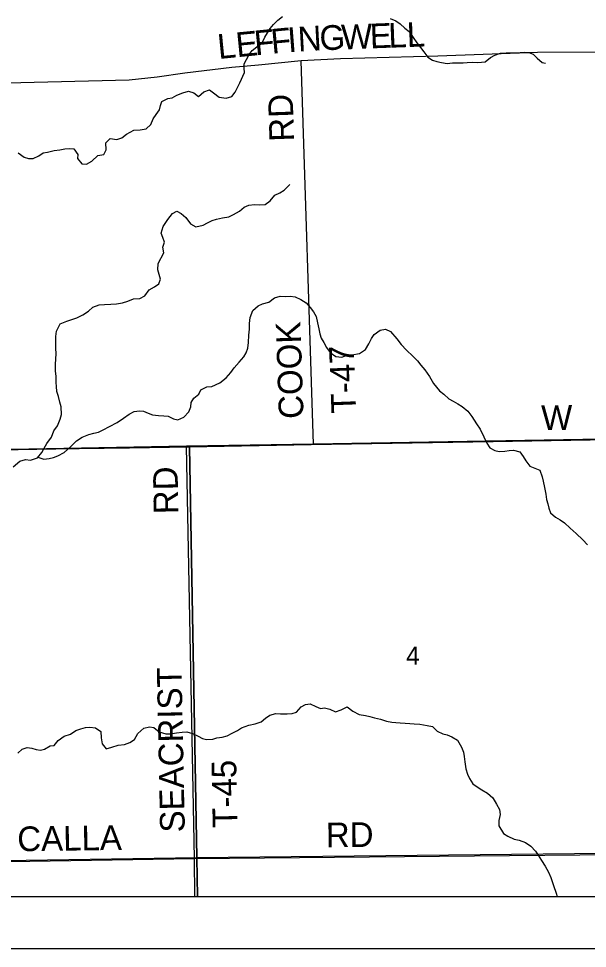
# Model space of a CAD drawing. Extents: x 0 to 34, y 0 to 22.
# Drawn here: x 5.396 to 6.705, y 13.887 to 16.025 of the extents above; entities that cross this region are included whole.
import ezdxf

# ---------------------------------------------------------------- set-up
doc = ezdxf.new("R2010")
doc.units = 0
for name, color, linetype in [('GM_X_Corporation', 7, 'Continuous'), ('GM_X_County_Road', 7, 'Continuous'), ('GM_X_County_Road_Text', 7, 'Continuous'), ('GM_X_Minor_River', 7, 'Continuous'), ('GM_X_Section_Text', 7, 'Continuous'), ('GM_X_Township_Road', 7, 'Continuous'), ('GM_X_Township_Road_Text', 7, 'Continuous'), ('SH_Data', 7, 'Continuous')]:
    doc.layers.add(name, color=color, linetype=linetype)

msp = doc.modelspace()

# ---------------------------------------------------------------- linework, layer by layer
at = {"layer": 'GM_X_Corporation'}
msp.add_lwpolyline([(2.9895, 20.1176), (2.9895, 14.989), (3.1061, 14.9902), (3.7218, 15.0051), (5.1362, 15.0301), (5.7825, 15.0418), (6.0746, 15.0468), (7.3134, 15.0684), (7.3375, 15.0689), (7.3129, 15.9614), (7.3097, 16.0633), (7.3049, 16.5704), (7.3046, 16.5913), (7.2998, 16.7507), (7.2943, 16.935), (7.2911, 17.0516), (7.2872, 17.1772), (7.283, 17.3071)], dxfattribs=at)
for points in [[(3.7367, 14.0069), (9.7895, 14.0069), (9.7895, 15.1275), (8.8365, 15.1033), (8.3803, 15.0917), (7.3375, 15.0689), (7.3134, 15.0684), (6.0746, 15.0468), (5.7825, 15.0418), (5.1362, 15.0301), (3.7218, 15.0051), (3.7359, 14.0555)], [(6.8006, 15.0584), (6.8205, 14.106), (5.8061, 14.0956), (5.789, 15.0408), (6.0694, 15.0457), (6.4885, 15.0527)], [(5.6513, 15.0385), (5.789, 15.0408), (5.8061, 14.0956), (4.774, 14.0793), (4.7584, 15.0257), (4.8116, 15.0266), (5.2442, 15.0326)], [(4.7752, 14.0069), (5.8075, 14.0069), (5.8061, 14.0956), (4.774, 14.0793)], [(5.8075, 14.0069), (6.8225, 14.0069), (6.8205, 14.106), (5.8061, 14.0956)]]:
    msp.add_lwpolyline(points, close=True, dxfattribs=at)
at = {"layer": 'GM_X_County_Road'}
msp.add_line((5.8019, 14.0069), (5.8006, 14.0939), dxfattribs=at)
for points in [[(3.722, 15.0045), (5.1364, 15.0296), (5.7827, 15.0412), (6.0748, 15.0463), (7.3136, 15.0678)], [(4.8042, 14.0781), (5.8006, 14.0939), (7.332, 14.1088)]]:
    msp.add_lwpolyline(points, dxfattribs=at)
at = {"layer": 'GM_X_Minor_River'}
for points in [[(5.9054, 15.8774), (5.9162, 15.9011), (5.9153, 15.9108), (5.9152, 15.9214), (5.9204, 15.9309), (5.9268, 15.9424), (5.9336, 15.952), (5.9483, 15.9635), (5.9581, 15.9723), (5.963, 15.9822), (5.9686, 15.9925), (5.975, 16.0021), (5.9825, 16.0117), (5.9927, 16.0212), (6.0032, 16.0301)], [(6.2509, 16.0253), (6.2639, 16.0197), (6.2738, 16.0133), (6.2846, 16.0031), (6.2945, 15.9956), (6.3038, 15.982), (6.3126, 15.9695), (6.3211, 15.9586), (6.3284, 15.9488), (6.338, 15.9367), (6.3484, 15.9292), (6.3587, 15.9262), (6.3693, 15.924), (6.3823, 15.9222), (6.3948, 15.9231), (6.4062, 15.9236), (6.4192, 15.9233), (6.4287, 15.9241), (6.4404, 15.925), (6.4526, 15.9243), (6.4701, 15.926), (6.4822, 15.9356), (6.492, 15.941), (6.5049, 15.9453), (6.5178, 15.9461), (6.5391, 15.9463), (6.5505, 15.9475), (6.5608, 15.948), (6.5703, 15.9469), (6.5799, 15.9432), (6.5898, 15.9338), (6.601, 15.924), (6.609, 15.9225)], [(5.3952, 15.7168), (5.4087, 15.7068), (5.4186, 15.7036), (5.4292, 15.7038), (5.4424, 15.7097), (5.4521, 15.7167), (5.4627, 15.7177), (5.4778, 15.7222), (5.491, 15.7232), (5.5027, 15.7253), (5.5129, 15.7267), (5.5232, 15.7253), (5.5321, 15.713), (5.5315, 15.7031), (5.5412, 15.6911), (5.5522, 15.6906), (5.5642, 15.6973), (5.5784, 15.7101), (5.592, 15.713), (5.5971, 15.723), (5.5968, 15.7397), (5.6069, 15.7494), (5.6221, 15.747), (5.6333, 15.751), (5.6442, 15.7592), (5.6614, 15.7683), (5.6754, 15.7697), (5.6898, 15.7715), (5.7006, 15.7819), (5.7057, 15.7946), (5.7127, 15.8046), (5.7201, 15.815), (5.7225, 15.8253), (5.7254, 15.8348), (5.7393, 15.8416), (5.7495, 15.8433), (5.7604, 15.8492), (5.7739, 15.8548), (5.7871, 15.8584), (5.7993, 15.8545), (5.8101, 15.846), (5.822, 15.8565), (5.8352, 15.8613), (5.8448, 15.8546), (5.8575, 15.8446), (5.8734, 15.8423), (5.8866, 15.8459), (5.894, 15.8556), (5.8995, 15.8663), (5.9054, 15.8774)], [(5.5183, 15.3336), (5.5296, 15.3373), (5.5439, 15.344), (5.557, 15.3526), (5.567, 15.3619), (5.5817, 15.3671), (5.5938, 15.3681), (5.6082, 15.3684), (5.6211, 15.369), (5.6354, 15.3716), (5.6471, 15.3752), (5.6603, 15.3808), (5.6747, 15.3815), (5.6863, 15.3878), (5.6967, 15.4013), (5.7086, 15.4087), (5.7184, 15.415), (5.7227, 15.4261), (5.7191, 15.4366), (5.7163, 15.4472), (5.7171, 15.462), (5.7303, 15.4862), (5.7278, 15.4995), (5.7314, 15.5113), (5.7278, 15.5215), (5.7238, 15.5317), (5.7288, 15.547), (5.7391, 15.5635), (5.7502, 15.577), (5.7604, 15.5822), (5.7703, 15.577), (5.7811, 15.5681), (5.7912, 15.5535), (5.8042, 15.5462), (5.8208, 15.5503), (5.8306, 15.5558), (5.8415, 15.5606), (5.8513, 15.5638), (5.8649, 15.5671), (5.8796, 15.5696), (5.8909, 15.5744), (5.904, 15.5826), (5.9152, 15.5912), (5.9261, 15.596), (5.939, 15.5974), (5.9515, 15.5969), (5.9636, 15.5975), (5.9752, 15.6064), (5.9855, 15.6188), (5.9972, 15.6247), (6.0069, 15.631), (6.02, 15.6434)], [(5.4403, 15.0165), (5.4541, 15.0122), (5.4659, 15.0139), (5.4761, 15.016), (5.4862, 15.0196), (5.5005, 15.0275), (5.515, 15.0407), (5.5295, 15.0546), (5.5419, 15.0629), (5.5573, 15.0689), (5.5694, 15.0717), (5.5799, 15.0746), (5.5908, 15.0794), (5.6055, 15.0869), (5.6227, 15.0963), (5.6377, 15.1065), (5.6504, 15.1159), (5.662, 15.1218), (5.6738, 15.1231), (5.6833, 15.1222), (5.6943, 15.1178), (5.7042, 15.1142), (5.7179, 15.1122), (5.7301, 15.1121), (5.7403, 15.1111), (5.7522, 15.1049), (5.7621, 15.1024), (5.776, 15.1084), (5.7875, 15.1208), (5.7926, 15.1327), (5.7931, 15.1425), (5.7994, 15.1525), (5.8106, 15.1615), (5.8157, 15.1715), (5.8289, 15.1782), (5.8406, 15.1795), (5.859, 15.1879), (5.8736, 15.1992), (5.8847, 15.2115), (5.8921, 15.2219), (5.9032, 15.2351), (5.9144, 15.2474), (5.9199, 15.257), (5.9235, 15.267), (5.9247, 15.2807), (5.9256, 15.297), (5.9272, 15.3107), (5.9273, 15.324), (5.9286, 15.3381), (5.9351, 15.3542), (5.9471, 15.3647), (5.9572, 15.3691), (5.9715, 15.3731), (5.985, 15.3833), (5.9978, 15.3866), (6.0111, 15.3864), (6.0209, 15.3866), (6.0327, 15.3857), (6.0457, 15.3791), (6.0576, 15.3717), (6.0669, 15.3609), (6.075, 15.3512), (6.0809, 15.3399), (6.0842, 15.3255), (6.0867, 15.3119), (6.0892, 15.3006), (6.092, 15.2904), (6.0987, 15.2806), (6.1049, 15.269), (6.1131, 15.2573), (6.1258, 15.2481), (6.1402, 15.2468), (6.1523, 15.2512), (6.1629, 15.2518), (6.1802, 15.2548), (6.1945, 15.2642), (6.2022, 15.2777), (6.208, 15.2895), (6.2139, 15.2991), (6.2281, 15.3085), (6.2402, 15.3114), (6.2516, 15.3059), (6.2664, 15.2888), (6.2765, 15.2757), (6.2888, 15.2626), (6.3031, 15.2492), (6.3143, 15.2384), (6.322, 15.2283), (6.3306, 15.2174), (6.3415, 15.2021), (6.3512, 15.1863), (6.3644, 15.1694), (6.3744, 15.1613), (6.386, 15.1512), (6.396, 15.1454), (6.4067, 15.1395), (6.417, 15.1336), (6.4297, 15.1224), (6.4394, 15.1101), (6.45, 15.0936), (6.4582, 15.0808)], [(5.3832, 14.9945), (5.3989, 15.0073), (5.4121, 15.011), (5.4235, 15.0101), (5.4393, 15.0153), (5.4493, 15.0273), (5.4548, 15.0376), (5.4611, 15.048), (5.4714, 15.0626), (5.4768, 15.0772), (5.4853, 15.0891), (5.4919, 15.1041), (5.4947, 15.1151), (5.494, 15.1322), (5.4911, 15.1435), (5.4875, 15.156), (5.4838, 15.1681), (5.4829, 15.1791), (5.4823, 15.1886), (5.4821, 15.2019), (5.4807, 15.2155), (5.4808, 15.2303), (5.4817, 15.2417), (5.4822, 15.2551), (5.4816, 15.2668), (5.4818, 15.2801), (5.4819, 15.2938), (5.4828, 15.3063), (5.4912, 15.3232), (5.507, 15.3296), (5.5183, 15.3336)], [(6.4582, 15.0808), (6.4668, 15.0635), (6.4735, 15.0492), (6.4805, 15.0379), (6.492, 15.0321), (6.5023, 15.0296), (6.5148, 15.0302), (6.525, 15.032), (6.5352, 15.0329), (6.5497, 15.029), (6.5574, 15.0185), (6.5633, 15.0084), (6.5723, 14.996), (6.5837, 14.9913), (6.5952, 14.9869), (6.6007, 14.9715), (6.6032, 14.9616), (6.6061, 14.9473), (6.6091, 14.9314), (6.6112, 14.9193), (6.614, 14.9094), (6.6165, 14.8992), (6.6201, 14.889), (6.632, 14.8786), (6.6424, 14.8727), (6.6523, 14.8657), (6.6651, 14.8538), (6.6789, 14.8415), (6.6944, 14.827), (6.7056, 14.8151)], [(5.6974, 14.3966), (5.7069, 14.3952), (5.7193, 14.3852), (5.7349, 14.3806), (5.7455, 14.3808), (5.7595, 14.3826), (5.7727, 14.3847), (5.7833, 14.3849), (5.7962, 14.3817), (5.8089, 14.3752), (5.8188, 14.37), (5.8287, 14.3676), (5.8427, 14.3686), (5.8525, 14.3711), (5.8646, 14.3728), (5.8759, 14.3764), (5.8872, 14.3824), (5.8996, 14.3883), (5.9093, 14.3946), (5.9259, 14.4002), (5.9406, 14.4035), (5.9541, 14.4083), (5.9642, 14.4165), (5.9739, 14.4239), (5.9879, 14.4276), (5.9989, 14.4267), (6.0137, 14.4266), (6.0254, 14.4272), (6.0359, 14.4308), (6.0463, 14.4428), (6.0565, 14.4479), (6.0667, 14.4496), (6.0797, 14.4434), (6.0904, 14.4387), (6.1002, 14.4404), (6.112, 14.4376), (6.1254, 14.4314), (6.1385, 14.4362), (6.1521, 14.4425), (6.1655, 14.4325), (6.18, 14.4252), (6.1945, 14.4228), (6.204, 14.4207), (6.2147, 14.4171), (6.2287, 14.414), (6.2428, 14.4101), (6.255, 14.4076), (6.2645, 14.4067), (6.2744, 14.4057), (6.2857, 14.4052), (6.2967, 14.4046), (6.3066, 14.4037), (6.3191, 14.4028), (6.3366, 14.4001), (6.3488, 14.3973), (6.3596, 14.3868), (6.3726, 14.3806), (6.3821, 14.3782), (6.3932, 14.3734), (6.4062, 14.3657), (6.4156, 14.3503), (6.42, 14.3386), (6.4217, 14.3284), (6.423, 14.3163), (6.4256, 14.3), (6.4292, 14.2879), (6.4336, 14.2781), (6.4414, 14.2657), (6.451, 14.2591), (6.4621, 14.2521), (6.4755, 14.2443), (6.4875, 14.2332), (6.4961, 14.2193), (6.5024, 14.2065), (6.5045, 14.1955), (6.5013, 14.1814), (6.5012, 14.1688), (6.5117, 14.1516), (6.5221, 14.1453), (6.5366, 14.1387), (6.548, 14.1363), (6.5629, 14.1309), (6.5752, 14.122), (6.5856, 14.1112), (6.5918, 14.1014), (6.5996, 14.0894), (6.6078, 14.0763), (6.6153, 14.0624), (6.6208, 14.0507), (6.6268, 14.0322), (6.6328, 14.0145), (6.6352, 14.0069)], [(5.3943, 14.336), (5.4044, 14.345), (5.4153, 14.3494), (5.4263, 14.3477), (5.4362, 14.3448), (5.4461, 14.3427), (5.4559, 14.3452), (5.4682, 14.353), (5.4781, 14.354), (5.4873, 14.3656), (5.5008, 14.3753), (5.5151, 14.3801), (5.5278, 14.3884), (5.5391, 14.3924), (5.5497, 14.3952), (5.5595, 14.3958), (5.5728, 14.3945), (5.5851, 14.386), (5.5861, 14.3716), (5.5879, 14.3576), (5.5976, 14.346), (5.6104, 14.3497), (5.6247, 14.3549), (5.6395, 14.3559), (5.6523, 14.3604), (5.6627, 14.3678), (5.6701, 14.3812), (5.6839, 14.3936), (5.6974, 14.3966)]]:
    msp.add_lwpolyline(points, dxfattribs=at)
at = {"layer": 'GM_X_Township_Road'}
for p, q in [((6.0748, 15.0463), (6.0463, 15.9282)), ((5.8006, 14.0939), (5.7827, 15.0412))]:
    msp.add_line(p, q, dxfattribs=at)
msp.add_lwpolyline([(7.3131, 15.9608), (7.0513, 15.9556), (6.7947, 15.9481), (6.5899, 15.9475), (6.3611, 15.9388), (6.1369, 15.9328), (6.0463, 15.9282), (5.9481, 15.9181), (5.8864, 15.9123), (5.7783, 15.8996), (5.7151, 15.8908), (5.6504, 15.8839), (5.1195, 15.8708)], dxfattribs=at)
at = {"layer": 'SH_Data'}
msp.add_line((2.8945, 13.8873), (9.8945, 13.8873), dxfattribs=at)

# ---------------------------------------------------------------- texts
at = {"layer": 'GM_X_County_Road_Text'}
for s, height, rotation, p in [('W', 0.0568, 0.7248, (6.5991, 15.0788)), ('RD', 0.05682, 0.4936, (6.1033, 14.1197)), ('CALLA', 0.05682, 0.796, (5.3932, 14.1105))]:
    msp.add_text(s, height=height, rotation=rotation, dxfattribs=at).set_placement(p)
at = {"layer": 'GM_X_Section_Text'}
msp.add_text('4', height=0.0419, rotation=0, dxfattribs=at).set_placement((6.2877, 14.5394))
at = {"layer": 'GM_X_Township_Road_Text'}
for s, height, rotation, p in [('W', 0.0568, 2.1364, (6.1395, 15.954)), ('E', 0.0568, 2.1392, (6.2053, 15.9565)), ('L', 0.0568, 2.1347, (6.2478, 15.958)), ('L', 0.0568, 2.1392, (6.2902, 15.9596)), ('E', 0.0568, 5.586, (5.8986, 15.9362)), ('F', 0.0568, 5.5825, (5.9409, 15.9404)), ('F', 0.0568, 5.3768, (5.979, 15.9441)), ('I', 0.0568, 4.4071, (6.0169, 15.9476)), ('N', 0.0568, 3.1198, (6.0399, 15.9494)), ('G', 0.0568, 2.1533, (6.0895, 15.9521)), ('L', 0.0568, 5.5844, (5.8563, 15.9321)), ('RD', 0.05682, 91.9758, (6.0303, 15.7432)), ('COOK', 0.05682, 91.9414, (6.052, 15.1057)), ('T-47', 0.05682, 92.1213, (6.1729, 15.1185)), ('RD', 0.05682, 90.9872, (5.7637, 14.8861)), ('SEACRIST', 0.05682, 91.1631, (5.7786, 14.1544)), ('T-45', 0.05682, 91.0603, (5.8996, 14.165))]:
    msp.add_text(s, height=height, rotation=rotation, dxfattribs=at).set_placement(p)

doc.saveas('drawing.dxf')
